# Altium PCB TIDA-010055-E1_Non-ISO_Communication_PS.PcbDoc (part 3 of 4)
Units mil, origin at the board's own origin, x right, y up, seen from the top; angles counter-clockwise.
Board outline 3937.01 x 3346.46 mil, 2 copper layers (Top Layer, Bottom Layer), stack 62 mil thick; 328 components, 142 nets, 761 pads, 214 vias.
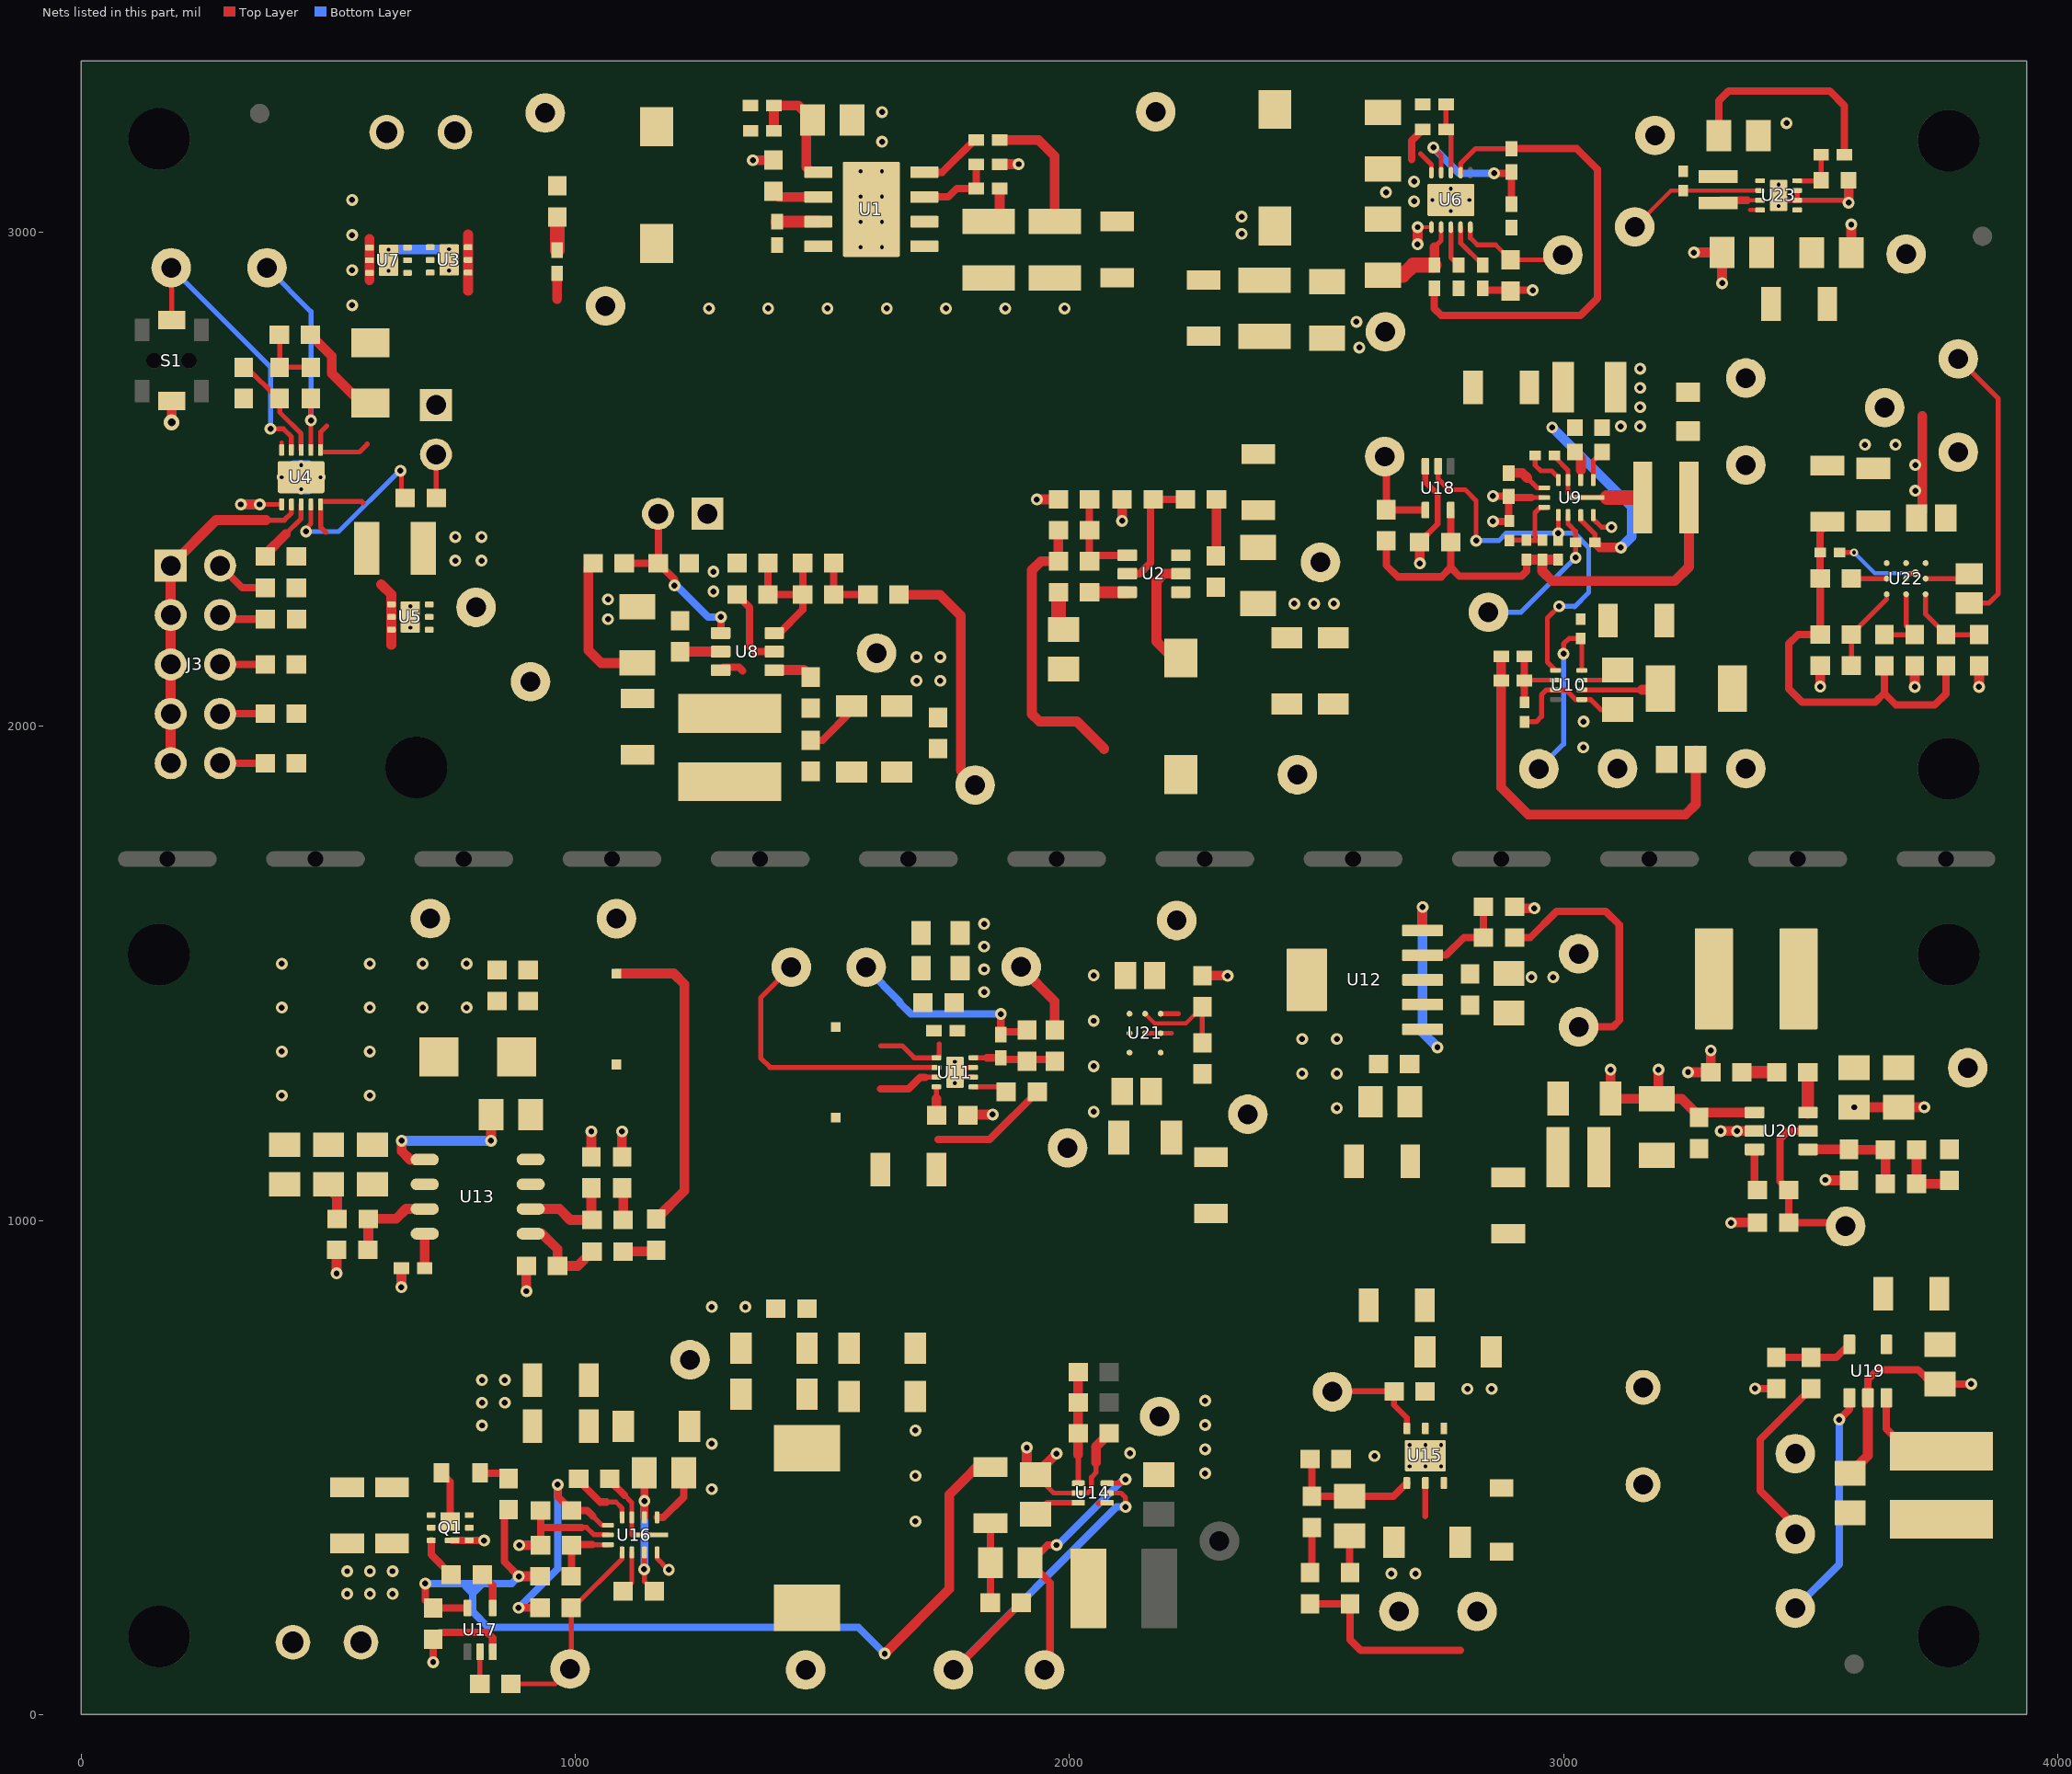
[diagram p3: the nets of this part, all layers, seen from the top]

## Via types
v1: diameter 24, hole 12, Top Layer to Bottom Layer, 179 vias
v2: diameter 19.68, hole 7.87, Top Layer to Bottom Layer, 28 vias
v3: diameter 19.68, hole 7.87, Top Layer to Bottom Layer, tented both sides, 4 vias
v4: diameter 16, hole 8, Top Layer to Bottom Layer, 2 vias
v5: diameter 32, hole 16, Top Layer to Bottom Layer, 1 vias

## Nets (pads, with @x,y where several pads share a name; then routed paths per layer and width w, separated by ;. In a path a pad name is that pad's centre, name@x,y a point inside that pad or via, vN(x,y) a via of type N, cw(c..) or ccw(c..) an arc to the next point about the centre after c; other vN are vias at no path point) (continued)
5V_LMR: C68.1 C69.1 C70.1 C71.1 C72.1 C74.1 L11.2 R63.1 R68.1 R76.2 R78.2 R85.1 R86.1 U17.5 | length 1977.8
  Top Layer w15: v1(696,265) 696,231.5 C74.1@712,215.5 712.2,215.29 U17.5@781.41,215.29 ; R78.2@865,414.5 856,405.5 856,309 v1(885.4,279.6)
  Top Layer w20: v1(885.4,279.6) R76.2@928.5,279.6 ; v1(1626,123) 1757,254 1757,445 1794,482 1813.08,501.08 R63.1@1840.01,501.08
  Bottom Layer w15: v1(696,265) 792,265 ; 777,265 777,260 792,245 811,264 811,265 ; v1(885.4,279.6) 870.8,265 792,265 ; v1(1626,123) 1573,176 824,176 792,208 792,265
5V_S: C25.1 C26.1 C27.2 C28.1 L4.2 R29.2 TP9.1 | length 497.4
  Top Layer w20: R29.2@1654.93,2266.49 1737.51,2266.49 1780,2224 1780,1910.29 TP9.1@1809,1881.29
24V: J5.2 R54.2 R55.2 R56.2 R82.2
  other v1: 538,244 584,244 630,244 538,290 584,290 630,290 811,585 811,631 857,631 811,677 857,677
24V/150MA: C61.1 D2.1 R71.1 R72.1 TP33.1 | length 385.9
  Top Layer w15: R72.1@2486.94,224.05 R71.1@2567.87,224.05 2567.87,151.53 2589.4,130 2791.4,130
+5V_P: C10.1 C11.1 C12.1 L2.2 R10.2 TP3.1 | length 591.1
  Top Layer w20: R10.2@1977.5,2397.3 C12.1@1977.5,2334.3 1942.3,2334.3 1924,2316 1924,2025 1939,2010 2015,2010 2070,1955 2070,1954
DC_I: C14.1 R51.2 R58.1 R59.1 R60.1 R61.1 TP10.1 U4.10 U5.4 U5.5 U5.6 | length 285.3
  Top Layer w10: 495,2392.4 484.15,2403.25 U4.10@484.15,2449.23 484.15,2455.18 567.22,2455.18 570,2452.4
  Top Layer w20: 607,2287.4 627.39,2267.01 U5.4@627.39,2246.94 U5.5@627.39,2221.35 U5.6@627.39,2195.76 627.39,2164.8
EN: R33.1 TP14.1 U9.9 | length 314.6
  Top Layer w10: U9.9@3009.11,2427.67 3009.11,2409.99 3024.32,2394.78 R33.1@3024.32,2372.1 v1(3024.32,2341.41)
  Bottom Layer w10: TP14.1@2848,2231 2913.9,2231 v1(3024.32,2341.41)
EN1: R88.1 R91.2 TP42.1 U20.5 | length 358.5
  Top Layer w15: U20.5@3494.74,1180.94 3453.94,1180.94 3438,1165 3438,1079.31 R88.1@3455.62,1061.69 R91.2@3455.62,995.69 3563.31,995.69 TP42.1@3571,988
FB: C34.2 R35.1 R37.2 U9.7 | length 147.3
  Top Layer w10: R37.2@2890,2376.41 2890.37,2376.78 C34.2@2925,2376.78 2925.69,2376.1 2942,2376.1 ; R35.1@2957,2376.78 2956.32,2376.1 2942,2376.1 ; U9.7@2960.88,2443.41 2953.32,2443.41 2942,2432.1 2942,2376.1
GND: C40.2 C42.2 C43.2 C44.2 C45.2 C46.1 C47.1 C48.1 C49.1 C51.2 C52.2 C53.2 C54.2 C55.2 C56.2 C58.2 C59.2 C60.2 C61.2 C62.2 C66.2 C67.2 C68.2 C69.2 C70.2 C71.2 C72.2 C73.2 C74.2 C76.2 C77.2 C79.2 C80.2 C81.2 C82.2 C83.2 C85.2 C86.2 C87.2 D1.2 J5.1 Q1.4 Q1.7 R42.1 R44.1 R48.1 R49.1 R50.1 R67.1 R73.1 R77.1 R84.1 R91.1 R92.1 R95.1 TP21.1 TP23.1 TP25.1 TP31.1 TP34.1 TP37.1 TP39.1 TP45.1 U11.2 U11.3 U11.9@1767.99,1299.75 U12.3 U12.6 U13.7 U14.2 U15.1 U15.5 U15.7@2720.27,523.66 U16.1 U16.6 U16.11 U17.3 U19.2 U20.1 U21.C1 U21.C2 U21.C3 | length 2923.4
  Top Layer w10: 1012.47,378.53 1022.47,378.53 1036.91,364.09 1065.19,364.09 U16.6@1065.88,363.4 ; U16.11@1165.29,327.97 1165.29,315.71 1188,293 v1(1189,293) ; U11.2@1805.39,1289.91 1777.83,1289.91 U11.9@1767.99,1299.75 1777.83,1309.6 U11.3@1805.39,1309.6 ; C60.2@1931.01,485.19 1968.01,448.19 U14.2@2017.87,448.19 2036.78,448.19 2044.54,455.96 2044.54,480.19 2053.54,489.19 2053.54,509.96
  Top Layer w12: C61.2@2656.94,348.54 C61.2@2656.94,356.42 ; 2720.27,401 U15.5@2720.27,468.54
  Top Layer w15: v1(712,106) C74.2@712,152.5 725.5,166 822,166 832.59,155.41 U17.3@832.59,126.71 ; Q1.7@750.35,352.41 v1@814.59,352.41 ; R77.1@929.5,342.6 929.5,381 ; C73.2@929.5,412.6 929.5,381 ; 1012.47,378.53 931.98,378.53 929.5,381 ; U16.1@1165.29,398.83 1177.83,398.83 1219,440 C67.2@1219,489.4 ; v1(3387.5,659.5) R84.1@3431,659.5 ; U19.2@3616,640.87 3616,678 3636,698 3717,698 3746,669 C76.2@3762,669 v1(3825,669)
  Top Layer w20: v1(516.62,892.91) R48.1@516.62,940.31 ; C56.2@647.6,903.16 647.74,903.02 v1(647.74,864.79) ; v1(886.4,342.6) R77.1@929.5,342.6 ; v1(900.72,856.8) R49.1@900.72,908.16 ; C58.2@1032.22,1128.66 v1(1032.22,1180.26) ; R50.1@1094.22,1128.66 v1(1094.22,1180.26) ; C40.2@1794.49,1212.75 1795.96,1214.23 v1(1844.52,1214.23) ; TP21.1@1902.39,1511.23 1969.99,1443.63 R42.1@1969.99,1385.25 R42.1@1969.99,1381.75 ; v1(1913.54,539.96) 1913.54,502.66 C60.2@1931.01,485.19 v1(1973.77,527.96) ; 2053.54,509.96 2053.54,541.56 2055.07,543.09 2055.07,543.76 R67.1@2080.5,569.19 ; R95.1@2269,1495.5 v1@2319.5,1495.5 ; R44.1@2900.97,1634.85 2904.06,1631.75 v1(2941,1631.75) ; v1(3095.15,1305.15) C81.2@3095.15,1247 3096.12,1246.03 C80.2@3188.61,1246.03 3239.02,1246.03 3276.61,1208.44 3286.51,1218.35 U20.1@3386.47,1218.35 ; C80.2@3192.03,1247 v1(3192.03,1305.15) ; v1(3339,995) 3339.69,995.69 R91.1@3392.62,995.69 ; v1(3530,1082) 3530.99,1081.01 R92.1@3578,1081.01 ; C77.2@3580,488 3616,524 U19.2@3616,640.87 ; v1(3588,1229) C83.2@3678,1229 v1(3730,1229)
  other v1: 2651.4,285 2700.4,285 815,352 1688,391 1276,456 1688,483 2274.54,487.96 2617.4,523 2122.54,528.96 2274.54,536.96 1276,548 1688,575 2274.54,585.96 2274.54,634.96 2805.4,659 2854.4,659 1276,825 1344,825 2049,1220 2541,1227.25 405.74,1252.79 583.74,1252.79 2471,1297.25 2541,1297.25 2049,1312 405.74,1341.79 583.74,1341.79 2471,1367.25 2541,1367.25 2049,1404 405.74,1430.79 583.74,1430.79 690.74,1430.79 779.74,1430.79 1827.39,1462.23 2935,1492.25 2979,1492.25 2320,1495 2049,1496 1827.39,1508.23 405.74,1519.79 583.74,1519.79 690.74,1519.79 779.74,1519.79 1827.39,1554.23 1827.39,1600.23
  other v2: 2688.62,502.01 2720.27,502.01 2751.93,502.01 2688.62,545.32 2720.27,545.32 2751.93,545.32 1767.99,1278.1 1767.99,1321.41
GND_P: C2.2 C5.1 C6.1 C8.2 C9.2 C10.2 C11.2 C13.2 C14.2 C15.2 C16.2 C17.2 C19.2 C20.2 C21.2 C22.2 C25.2 C26.2 C27.1 C28.2 C29.2 C30.1 C31.2 C32.2 C35.2 C36.2 C37.2 C38.2 C75.2 C88.2 C89.2 C91.2 C92.2 C93.2 J2.2 J4.1 R4.1 R5.1 R6.1 R11.1 R12.1 R25.1 R26.1 R27.1 R30.1 R32.1 R37.1 R39.1 R62.1 R99.1 R102.1 R103.1 R108.1 S1.1 TP2.1 TP5.1 TP8.1 TP11.1 TP12.1 TP16.1 TP18.1 TP47.1 TP50.1 U1.1 U1.9@1599,3046.55 U2.1 U4.6 U5.1 U5.2 U5.3 U5.7@665.78,2221.35 U6.10 U6.11 U7.4 U7.5 U7.6 U8.2 U9.1 U9.6 U9.11 U10.3 U10.5 U18.3 U22.C2 U23.2 U23.3 U23.9@3435.31,3074.72 | length 2445.9
  Top Layer w10: v1(360.9,2449.23) U4.6@405.41,2449.23 ; 2711,3158.61 2732.53,3137.08 U6.10@2732.53,3120.65 ; R39.1@2921.37,2009.15 2944.68,2009.15 2955.37,2019.83 2955.37,2063.83 2965.52,2073.99 U10.3@2983.79,2073.99 3004.14,2073.99 3023.82,2054.3 U10.5@3036.94,2054.3 3054.89,2054.3 3075.37,2033.83 C35.2@3109.37,2033.83 ; 2935,2463.1 U9.6@2960.88,2463.1 ; U9.11@3060.29,2427.67 3060.29,2419.81 3077,2403.1 v1(3097,2403.1) ; U9.1@3060.29,2498.53 3060.29,2537.84 C32.2@3077.76,2555.3 ; U23.9@3435.31,3074.72 3445.15,3064.88 U23.2@3472.71,3064.88 ; U23.3@3472.71,3084.57 U23.2@3472.71,3064.88 ; v1(3577,3060) 3572.12,3064.88 U23.2@3472.71,3064.88
  Top Layer w12: C75.2@2708.5,2373 2745,2409.5 2745,2470 2720.41,2494.59 U18.3@2720.41,2526.29
  Top Layer w15: R32.1@1326.93,2266.49 1352.41,2241.02 1352.41,2161.23 1362.32,2151.32 U8.2@1402.34,2151.32 ; C28.2@1476.21,1971.82 1500,1971.82 1559.21,2031.02 C25.2@1559.21,2041.25 ; 2692.5,3147.62 2692.5,3185.62 R26.1@2714.88,3208 ; C20.2@2836.5,2886.38 2840.03,2882.85 v1(2937.68,2882.85) ; v1(2857,2415.1) R37.1@2889,2415.1 ; v1(2857,2466.1) 2888.38,2466.1 C37.2@2889,2465.48 ; R37.1@2890,2415.78 2889,2416.78 C37.2@2889,2465.48 ; 2935,2463.1 2891.38,2463.1 C37.2@2889,2465.48
  Top Layer w20: v5(182.74,2615.31) S1.1@182.74,2658.65 ; v1(322.9,2449.23) v1(360.9,2449.23) ; 583.23,2903.22 U7.6@583.23,2917.81 U7.5@583.23,2943.4 U7.4@583.23,2968.99 583.23,2986.63 ; 963,2865.4 R5.1@963,2916.93 ; v1(1359.13,3145.88) 1400.83,3145.88 C2.2@1401,3146.05 ; R4.1@1858.62,3137.55 1858.94,3137.88 v1(1897.13,3137.88) ; v1(1934,2459.3) R12.1@1977.5,2459.3 ; v1(2106.5,2415.8) R11.1@2106.5,2459.3 ; C75.2@2708.5,2373 2709,2372.5 v1(2709,2330) ; v1(3264,2959) C92.2@3321,2959 v1(3321,2897) v1@3321,2895 ; v1(3519.5,2080.5) R99.1@3519.5,2123 ; R108.1@3576.56,3105 3577,3104.56 v1(3577,3060) ; C91.2@3582.31,2958.72 v1(3582.31,3015.72) ; v1(3711,2080) R102.1@3711,2122.5 ; C89.2@3714.47,2422 3726,2433.53 3726,2628 ; v1(3841,2080) R103.1@3841,2122.5
  other v1: 3040,1957.4 3040.37,2009.83 1690.41,2092.23 1738.41,2092.23 1690.41,2140.23 1738.41,2140.23 1066,2217 2455,2248.3 2495,2248.3 2535,2248.3 1066,2257 1279.41,2273.23 1279.41,2313.23 757,2335.4 810,2335.4 757,2383.4 810,2383.4 3712,2477 3712,2529 3610,2570 3672,2570 3116,2607.1 3155,2607.1 3155,2646.1 3155,2685.1 3155,2724.1 2586.68,2766.85 2580.68,2818.85 1270.13,2845.88 1390.13,2845.88 1510.13,2845.88 1630.13,2845.88 1750.13,2845.88 1870.13,2845.88 1990.13,2845.88 548,2852.4 548,2923.4 548,2994.4 2697.5,3062.62 548,3065.4 2640.68,3080.85 2697.5,3102.62 1620.65,3183.32 3451.31,3221 1620.65,3243.32
  other v2: 665.78,2199.7 665.78,2243 1577.35,3020.96 1620.65,3020.96 2771.9,3042.9 3435.31,3053.07 2734.5,3065.54 2809.3,3065.54 1577.35,3072.14 1620.65,3072.14 2771.9,3088.17 3435.31,3096.38
  other v3: 1577.35,2969.78 1620.65,2969.78 1577.35,3123.32 1620.65,3123.32
NetC1_1: C1.1 U1.7 | length 83.6
  Top Layer w25: C1.1@1408.13,3021.5 1408.18,3021.55 U1.7@1491.72,3021.55
NetC1_2: C1.2 L1.1 U1.8
NetC2_1: C2.1 U1.6 | length 95.5
  Top Layer w20: C2.1@1401,3083.06 1412.5,3071.55 U1.6@1491.72,3071.55
NetC3_2: C3.2 R5.2 | length 66.9
  Top Layer w30: R5.2@963,2964.17 C3.2@963,3031.06
NetC4_2: C4.2 R3.1 R6.2 U1.5 | length 271.4
  Top Layer w20: C4.2@1402,3205.55 1401.62,3205.93 R3.1@1401.62,3256.55 1451,3256.55 R6.2@1480,3227.55 1467.13,3214.68 1467.13,3131.88 1477.45,3121.55 U1.5@1491.72,3121.55
NetC5_2: C5.2 C6.2 R1.2 R2.2 R58.2 U1.2 | length 333.5
  Top Layer w20: C6.2@1836,3021.64 1858.62,3044.26 R2.2@1858.62,3088.55 ; R1.2@1858.62,3186.55 1937.45,3186.55 1970,3154 C5.2@1970,3021.64
NetC7_1: C7.1 L2.1 U2.2 | length 246.5
  Top Layer w20: L2.1@2225,2122.86 2176,2171.86 2176,2293.3 2191.6,2308.9 U2.2@2225.27,2308.9
NetC7_2: C7.2 R7.2 | length 79.3
  Top Layer w30: R7.2@1977.5,2271.3 1977.5,2206.8 C7.2@1988,2196.3
NetC8_1: C8.1 C9.1 R8.2 R59.2 U2.3 | length 115.1
  Top Layer w20: C8.1@2296,2344.8 2297.5,2346.29 R8.2@2297.5,2459.3
NetC12_2: C12.2 R10.1 R12.2 U2.4 | length 206.5
  Top Layer w15: R12.2@2040.5,2459.3 R10.1@2040.5,2397.3 C12.2@2040.5,2334.3 2052.5,2346.3 U2.4@2117,2346.3
NetC13_1: C13.1 J1.1 J2.1 R13.2 U3.4 U3.5 U3.6 U4.1 | length 475.9
  Top Layer w10: 496.78,2608.35 484.15,2595.72 U4.1@484.15,2559.47 484.15,2552.72 486.78,2555.35 562.78,2555.35 578.78,2571.35
  Top Layer w20: R13.2@463.82,2792.35 506.78,2749.39 506.78,2714.35 566.8,2654.33 C13.1@584.78,2654.33 ; 782.71,2881.69 U3.4@782.71,2918.46 U3.5@782.71,2944.06 U3.6@782.71,2969.65 782.71,2995.69
NetC15_1: C15.1 C16.1 C17.1 R16.2 R60.2 U6.2 | length 195
  Top Layer w10: 2738.5,2969.62 2752.22,2983.34 U6.2@2752.22,3010.42
  Top Layer w20: R16.2@2738.5,2933.62 2738.5,2969.62
  Top Layer w30: C17.1@2634.5,2912.95 2674.83,2912.95 2695.5,2933.62 R16.2@2738.5,2933.62
NetC18_1: C18.1 U4.8 | length 134.9
  Top Layer w10: 413.78,2389.35 444.78,2420.35 U4.8@444.78,2449.23
  Top Layer w20: C18.1@372.28,2344.35 372.28,2347.85 413.78,2389.35
NetC18_2: C18.2 R18.1 R20.1 R21.1 R22.1 R23.1 R24.1 U4.5 U4.11@444.78,2504.35 | length 164.2
  Top Layer w8: U4.5@405.41,2559.47 405.41,2575.02
  Bottom Layer w20: v2(405.41,2504.35) 430.02,2528.96 v2(444.78,2528.96) 459.54,2528.96 v2(484.15,2504.35) 459.54,2479.74 v2(444.78,2479.74)
NetC20_1: C20.1 U6.4 | length 95.4
  Top Layer w10: U6.4@2791.59,3010.42 2791.59,2978.54 C20.1@2836.5,2933.62
NetC21_1: C21.1 C22.1 R28.2 R61.2 U8.5 | length 372.2
  Top Layer w20: R28.2@1035.71,2330.32 1026,2320.61 1026,2154.23 1052,2128.23 C21.1@1125.21,2128.23 ; C22.1@1212.21,2150.82 1212.7,2151.32 U8.5@1294.07,2151.32
NetC23_1: C23.1 U8.1 | length 80
  Top Layer w20: U8.1@1402.34,2113.92 1462.22,2113.92 C23.1@1476.41,2099.73
NetC23_2: C23.2 L4.1 U8.6 | length 49.7
  Top Layer w15: U8.6@1294.07,2113.92 1299.72,2119.56 1331.08,2119.56 1338.41,2112.23
NetC24_1: C24.1 R29.1 R31.2 | length 133
  Top Layer w15: C24.1@1522.93,2330.49 R31.2@1522.93,2266.49 R29.1@1591.93,2266.49
NetC24_2: C24.2 C29.1 R31.1 R32.2 U8.3 | length 305.8
  Top Layer w15: C29.1@1389.93,2330.49 R32.2@1389.93,2266.49 R31.1@1459.93,2266.49 ; U8.3@1402.34,2188.72 1412.91,2188.72 1459.93,2235.75 R31.1@1459.93,2266.49 ; C24.2@1459.93,2330.49 R31.1@1459.93,2266.49
NetC30_2: C30.2 C31.1 C32.1 R33.2 R51.1 U9.2 U9.10 | length 505
  Top Layer w10: U9.10@3034.7,2427.67 3034.7,2417.4 3063.69,2388.41 R33.2@3063.69,2372.1 ; U9.2@3034.7,2498.53 3034.7,2518.8 3035,2519.1
  Top Layer w20: C32.1@3022.64,2555.3 3035,2542.94 3035,2519.1 ; R33.2@3063.69,2372.1 3073.78,2362 v1(3116,2362)
  Bottom Layer w20: v1(2977,2605.1) 3138,2444.1 3138,2384 v1(3116,2362)
NetC33_1: C33.1 U9.4 | length 82
  Top Layer w10: C33.1@2942.32,2548.1 2942.32,2528.78 2954,2517.1 2976,2517.1 2989.43,2503.67 U9.4@2989.43,2498.53
NetC33_2: C33.2 L5.1 U9.3 U9.12@3047.02,2463.1 | length 243
  Top Layer w10: C33.2@2981.69,2548.1 2981.69,2545.57 3009.11,2518.15 U9.3@3009.11,2498.53 3009.11,2470.99 3017,2463.1 U9.12@3047.02,2463.1 3088,2463.1
  Top Layer w30: 3088,2463.1 L5.1@3160.35,2463.1
NetC35_1: C35.1 R36.2 R52.1 U10.7 | length 78.1
  Top Layer w10: U10.7@3036.94,2093.67 3095.71,2093.67 C35.1@3109.37,2107.33
NetC39_2: C39.2 R38.1 R39.2 U10.2 | length 156.6
  Top Layer w10: R38.1@2920.99,2092.83 2921.83,2093.67 U10.2@2983.79,2093.67
  Top Layer w15: C39.2@2920.99,2141.83 R38.1@2920.99,2092.83 2920.99,2048.89 R39.2@2921.37,2048.52
NetC40_1: C40.1 R40.1 R53.1 U11.8 | length 297.6
  Top Layer w10: 1730.59,1246.23 U11.8@1730.59,1270.23
  Top Layer w15: 1734,1163.64 1838.43,1163.64 R40.1@1935.01,1260.23
  Top Layer w20: C40.1@1730.59,1213.66 1730.59,1246.23
NetC41_1: C41.1 C42.1 C43.1 C44.1 C45.1 L7.2 R41.2 TP20.1 U11.5 | length 563.9
  Top Layer w10: 1617.99,1353.46 1661.16,1353.46 1685.34,1329.28 U11.5@1730.59,1329.28 1736.39,1335.09 1736.39,1357.23
  Top Layer w15: v1(1860.99,1417.83) C41.1@1860.99,1376.38 1866.37,1381.75 R41.2@1913.99,1381.75
  Bottom Layer w15: TP20.1@1585.99,1510.75 TP20.1@1587.26,1509.49 ; TP20.1@1588.52,1510.75 1657.02,1442.25 1657.02,1439.73 1678.92,1417.83 v1(1860.99,1417.83)
NetC41_2: C41.2 R41.1 R42.2 U11.4 | length 166.1
  Top Layer w10: U11.4@1805.39,1329.28 1832.39,1329.28
  Top Layer w15: 1832.39,1329.28 1832.54,1329.13 C41.2@1860.99,1329.13 1864.37,1325.75 1913.99,1325.75 R42.2@1969.99,1325.75
NetC46_2: C46.2 C48.2 R57.1 U12.1 U12.5 | length 344
  Top Layer w20: U12.5@2714.6,1586.85 v1(2714.6,1634.35)
  Bottom Layer w20: v1(2714.6,1634.35) 2714.6,1380.41 v1(2744.67,1350.34)
NetC47_2: C47.2 C49.2 R43.2 TP22.1 U12.2 | length 526.6
  Top Layer w15: R43.2@2900.97,1572.85 2933.09,1572.85 2986,1625.75 3085.65,1625.75 3112.81,1598.6 3112.81,1404.6 3100.06,1391.85 TP22.1@3030.47,1391.85
NetC50_1: C50.1 D1.1 L8.1 U13.8
NetC50_2: C50.2 U13.1 | length 308.6
  Top Layer w20: v1(648.27,1161.31) 648.27,1140.26 665.37,1123.16 U13.1@694.94,1123.16 ; v1(829.22,1161.31) C50.2@829.22,1214.16
  Bottom Layer w20: v1(648.27,1161.31) v1(829.22,1161.31)
NetC53_1: C53.1 C54.1 C55.1 R46.2 R55.1 R56.1 U13.2 | length 80.1
  Top Layer w20: C54.1@493.22,1073.16 517.72,1048.66 R46.2@517.72,1003.16
NetC56_1: C56.1 U13.4 | length 70
  Top Layer w20: C56.1@694.84,903.16 694.94,903.26 U13.4@694.94,973.16
NetC57_1: C57.1 C58.1 U13.6 | length 198.5
  Top Layer w20: U13.6@909.5,1023.16 967.37,1023.16 989.37,1001.16 C57.1@1033.72,1001.16 1032.22,1002.67 C58.1@1032.22,1065.67
NetC57_2: C57.2 R50.2 | length 65.5
  Top Layer w20: R50.2@1094.22,1065.67 1096.72,1063.17 C57.2@1096.72,1001.16
NetC60_1: C60.1 R63.2 R64.1 R65.2 U14.3 | length 257.8
  Top Layer w11: C60.1@1931.01,405.19 1954.32,428.51 U14.3@2017.87,428.51
  Top Layer w15: R64.1@1839.51,226.19 1840.01,226.69 R65.2@1840.01,307.19 ; R65.2@1840.01,307.19 R63.2@1840.01,387.3
NetC62_1: C62.1 L10.1 R68.2 R69.1 U15.2
NetC63_1: C63.1 R70.1 R73.2 U15.4 | length 280.6
  Top Layer w15: R73.2@2486.87,516.96 2490.37,513.47 C63.1@2490.37,441.54 R70.1@2566.87,441.54 2655.87,441.54 U15.4@2682.87,468.54
NetC63_2: C63.2 R72.2 | length 92.9
  Top Layer w15: R72.2@2486.94,287.04 2490.37,290.47 C63.2@2490.37,378.55
NetC64_2: C64.2 R66.1 R67.2 U14.1 | length 225.5
  Top Layer w11: 2017.51,525.96 2017.51,468.24 U14.1@2017.87,467.88
  Top Layer w20: 2017.51,525.96 R67.2@2017.51,569.19 ; R67.2@2017.51,569.19 C64.2@2017.51,693.19
NetC65_1: C65.1 U16.4 | length 133.7
  Top Layer w10: 1063,430 1082,430 1094.43,417.57 U16.4@1094.43,398.83
  Top Layer w15: C65.1@1006.5,477.4 1006.5,473.5 1050,430 1063,430
NetC65_2: C65.2 L11.1 TP35.1 U16.3 U16.12@1152.02,363.4 | length 170.4
  Top Layer w10: 1099,444 1114.11,428.89 U16.3@1114.11,398.83 1114.11,363.4 U16.12@1152.02,363.4
  Top Layer w15: C65.2@1069.5,477.4 1069.5,473.5 1099,444
NetC66_1: C66.1 C67.1 R54.1 R74.2 R82.1 U16.2 U16.10 | length 311
  Top Layer w10: U16.10@1139.7,327.97 1139.7,269.2 R74.2@1159.5,249.4
  Top Layer w15: C67.1@1139,489.4 1139.7,488.7 v1(1139.7,432) U16.2@1139.7,398.83
  Bottom Layer w15: v1@1139.7,298.58 v1(1139.7,432)
  other v1: 1139,294
NetC76_1: C76.1 R85.2 U19.4
NetC77_1: C77.1 L12.2 R83.2 TP26.1 | length 366.6
  Top Layer w15: TP26.1@3469,365 3469,382 3398,453 3398,556.5 R83.2@3501,659.5
NetC78_1: C78.1 R87.2 | length 70.5
  Top Layer w25: C78.1@3360.99,1300 R87.2@3431.5,1300
NetC78_2: C78.2 L14.1 U20.2 | length 158.5
  Top Layer w20: v1(3252,1300) C78.2@3298,1300 v1(3298,1344) ; v1(3318,1181) 3318.06,1180.94 v1(3351.06,1180.94) U20.2@3386.47,1180.94
NetC79_1: C79.1 C80.1 L13.2 R88.2 U20.3 | length 84.4
  Top Layer w15: U20.3@3386.47,1143.54 3386.47,1067.84 R88.2@3392.62,1061.69
NetC81_1: C81.1 L13.1 R86.2
NetC82_1: C82.1 C83.1 L14.2 R90.2 TP41.1
NetC84_1: C84.1 R89.2 R90.1 | length 138.4
  Top Layer w20: R89.2@3714.5,1143 C84.1@3714.5,1074 3773.99,1074 R90.1@3781,1081.01
NetC84_2: C84.2 R89.1 R92.2 U20.4 | length 226.4
  Top Layer w20: U20.4@3494.74,1143.54 3495.2,1144 R92.2@3578,1144 3579,1143 R89.1@3651.5,1143 C84.2@3651.5,1074
NetC85_1: C85.1 C86.1 R93.1 R94.2 TP43.1 U21.A2 U21.A3 U21.B2 | length 53
  Top Layer w10: U21.B2@2153,1379 U21.A2@2184.5,1379 2206,1379
NetC87_1: C87.1 TP44.1 U21.A1 | length 35.4
  Top Layer w10: U21.A1@2184.5,1418.37 2219.93,1418.37
NetC89_1: C89.1 TP46.1 U22.C1
NetC90_1: C90.1 U22.B1 | length 92.2
  Top Layer w10: U22.B1@3732.74,2299 3811.47,2299 C90.1@3821,2308.53
NetC90_2: C90.2 TP48.1 | length 575.6
  Top Layer w10: TP48.1@3799,2744 3880,2663 3880,2269 3860.47,2249.47 C90.2@3821,2249.47
NetC91_1: C91.1 C92.1 R105.2 U23.1 U23.8 | length 20.9
  Top Layer w8: 3377,3045.2 U23.8@3397.91,3045.2
NetC93_1: C93.1 L15.2 R106.2 R107.2 TP49.1 U23.5 | length 444.7
  Top Layer w15: C93.1@3314.31,3195.72 3314.31,3266.31 3334,3286 3539,3286 3568.62,3256.38 R106.2@3568.62,3157
NetD2_2: D2.2 L10.2 U15.6
NetD3_1: D3.1 Q1.1 Q1.2 Q1.5 Q1.6 Q1.8 | length 105.7
  Top Layer w15: D3.1@728.63,489 746.61,471.02 Q1.8@746.61,390.8
NetD3_2: D3.2 R78.1 | length 68.9
  Top Layer w15: D3.2@807.37,489 808.37,488 854.5,488 R78.1@865,477.5 ; R78.1@865,475 R78.1@871.5,475
NetJ1_2: J1.2 R9.2 | length 88.2
  Top Layer w10: J1.2@717.78,2550.35 718.28,2549.85 R9.2@718.28,2462.35
NetJ3_1: J3.1 J3.3 J3.5 J3.7 J3.9 U4.7 | length 724.9
  Top Layer w10: 373.78,2417.35 410.78,2417.35 425.1,2431.67 U4.7@425.1,2449.23
  Top Layer w20: J3.9@180.78,1925.35 J3.7@180.78,2025.35 J3.5@180.78,2125.35 J3.3@180.78,2225.35 J3.1@180.78,2325.35 J3.1@183.78,2328.35 ; J3.1@183.78,2309.35 J3.1@183.78,2328.35 ; 373.78,2417.35 272.78,2417.35 J3.1@183.78,2328.35
NetJ3_2: J3.2 R20.2 | length 110.1
  Top Layer w15: J3.2@280.78,2325.35 325.78,2280.35 R20.2@372.28,2280.35
NetJ3_4: J3.4 R21.2 | length 96.6
  Top Layer w15: J3.4@281.78,2226.35 J3.4@280.78,2225.35 289.13,2217 R21.2@372.5,2217
NetJ3_6: J3.6 R22.2 | length 91.5
  Top Layer w15: J3.6@280.78,2125.35 R22.2@372.28,2125.35
NetJ3_8: J3.8 R23.2 | length 91.5
  Top Layer w15: J3.8@280.78,2025.35 R23.2@372.28,2025.35
NetJ3_10: J3.10 R24.2 | length 91.5
  Top Layer w15: J3.10@280.78,1925.35 R24.2@372.28,1925.35
NetJ4_2: J4.2 R28.1 R30.2 U8.4 | length 381
  Top Layer w15: R28.1@1098.7,2330.32 R30.2@1167.71,2330.32 ; J4.2@1167.21,2430.32 1167.71,2429.82 R30.2@1167.71,2330.32 ; v1(1200.41,2285.23) 1200.41,2297.62 R30.2@1167.71,2330.32 ; U8.4@1294.07,2188.72 1294.41,2189.06 v1(1294.41,2221.23)
  Bottom Layer w15: v1(1200.41,2285.23) 1204.41,2285.23 1268.41,2221.23 v1(1294.41,2221.23)
NetL3_1: L3.1 U6.1 | length 62.7
  Top Layer w8: v1(2704.7,3010.42) U6.1@2732.53,3010.42
  Top Layer w20: v1(2704.5,2975.62) 2704.7,2975.83 v1(2704.7,3010.42)
  other v1: 2348.3,2996.83 2348.5,3031.62
NetL6_1: L6.1 U10.6 | length 160.2
  Top Layer w10: U10.6@3036.94,2073.99 3159,2073.99
  Top Layer w20: 3159,2073.99 3193.75,2073.99 L6.1@3196.17,2076.4
NetL7_1: L7.1 U11.7 | length 122.2
  Top Layer w10: 1708.39,1289.91 U11.7@1730.59,1289.91
  Top Layer w15: 1617.99,1266.05 1674.53,1266.05 1697.7,1289.22 1708.39,1289.22
NetL9_1: L9.1 U14.4 | length 18.3
  Top Layer w10: 2058.48,426.96 2060.03,428.51 U14.4@2076.14,428.51
NetL12_1: L12.1 U19.3 | length 192.8
  Top Layer w15: U19.3@3653.4,640.87 3653.4,578.6 3699.1,532.9 L12.1@3765,532.9
NetL15_1: L15.1 U23.7 | length 87.2
  Top Layer w8: 3372,3064.88 U23.7@3397.91,3064.88
  Top Layer w15: L15.1@3313,3059.43 3318.46,3064.88 3372,3064.88
NetQ1_3: Q1.3 R80.1 | length 86.1
  Top Layer w15: Q1.3@708.23,352.41 708.23,323.28 R80.1@748.5,283
NetR1_1: R1.1 U1.4 | length 132
  Top Layer w15: U1.4@1706.28,3121.55 1742.5,3121.55 1807.5,3186.55 R1.1@1811.38,3186.55
NetR2_1: R2.1 R4.2 U1.3 | length 161.1
  Top Layer w15: U1.3@1706.28,3071.55 1754.8,3071.55 1771.8,3088.55 R2.1@1811.38,3088.55 R4.2@1811.38,3137.55
NetR7_1: R7.1 U2.6 | length 76.6
  Top Layer w25: R7.1@2040.5,2271.3 2040.69,2271.5 U2.6@2117,2271.5
NetR8_1: R8.1 R11.2 U2.5 | length 251.6
  Top Layer w15: U2.5@2117,2308.9 2141.6,2308.9 2164,2331.3 2164,2453.8 R11.2@2169.5,2459.3 R8.1@2234.5,2459.3
NetR9_1: R9.1 U4.9 | length 364.3
  Top Layer w10: v1(454.78,2394.35) 451.78,2397.35 464.47,2410.04 U4.9@464.47,2449.23 ; v1(645.78,2517.35) 647.78,2517.35 647.78,2469.85 R9.1@655.28,2462.35
  Bottom Layer w10: v1(454.78,2394.35) 520.78,2394.35 644.78,2518.35 v1(645.78,2517.35)
NetR13_1: R13.1 R14.1 R15.2 | length 128.7
  Top Layer w10: R13.1@400.83,2792.35 401.32,2791.85 R15.2@401.32,2726.85 R14.1@464.32,2726.85
NetR14_2: R14.2 TP6.1 U4.2 | length 450.3
  Top Layer w10: R14.2@464.32,2663.85 464.47,2663.71 U4.2@464.47,2559.47
  Bottom Layer w10: TP6.1@375.78,2928.35 464.78,2839.35 v1(464.78,2619.35)
NetR15_1: R15.1 R18.2 U4.3 | length 221.5
  Top Layer w10: R18.2@328.32,2726.85 334.28,2726.85 397.28,2663.85 R15.1@401.32,2663.85 401.32,2635.81 444.78,2592.35 U4.3@444.78,2559.47
NetR16_1: R16.1 R19.2 U6.7 | length 970.5
  Top Layer w10: U6.7@2791.59,3120.65 2791.59,3138.71 2822.04,3169.16 R19.2@2887.5,3169.16
  Top Layer w15: R16.1@2738.5,2886.38 2738.5,2845.62 2752.5,2831.62 3034.46,2831.62 3068.68,2865.85 3068.68,3127.32 3026.84,3169.16 R19.2@2894.5,3169.16
NetR17_1: R17.1 R26.2 U6.8 | length 142.4
  Top Layer w10: R17.1@2762.12,3259 R26.2@2762.12,3208 2771.9,3198.22 U6.8@2771.9,3120.65
NetR19_1: R19.1 R27.2 U6.9 | length 303.3
  Top Layer w10: v1(2736.5,3171.62) 2752.22,3155.91 U6.9@2752.22,3120.65
  Top Layer w15: v1(2859.5,3119.62) 2892.21,3119.62 R19.1@2894.5,3121.91 R27.2@2894.5,3056.62
  Bottom Layer w15: v1(2736.5,3171.62) 2788.5,3119.62 v1(2859.5,3119.62)
NetR25_2: R25.2 U6.3 | length 83.3
  Top Layer w10: U6.3@2771.9,3010.42 2771.9,2949.22 R25.2@2787.5,2933.62
NetR36_1: R36.1 TP17.1 U10.8 | length 378.3
  Top Layer w10: v1(3000,2147) 3000,2167 3010.83,2177.83 R36.1@3034.68,2177.83 3036.94,2175.57 U10.8@3036.94,2113.36
  Bottom Layer w10: TP17.1@2950,1914 3000,1964 v1(3000,2147)
NetR40_2: R40.2 U11.1 | length 70.8
  Top Layer w10: U11.1@1805.39,1270.23 1862.02,1270.23 R40.2@1872.02,1260.23
NetR43_1: R43.1 R44.2 U12.4 | length 200.3
  Top Layer w15: U12.4@2714.6,1536.85 2762.6,1536.85 2798.6,1572.85 R43.1@2837.98,1572.85 R44.2@2837.98,1634.85
NetR45_1: R45.1 R47.2 | length 67.5
  Top Layer w20: R47.2@1096.72,937.16 1160.72,937.16 R45.1@1163.22,939.67
NetR46_1: R46.1 R48.2 U13.3 | length 188.6
  Top Layer w20: R48.2@582.22,937.66 580.72,939.16 R46.1@580.72,1003.16 637.12,1003.16 657.12,1023.16 U13.3@694.94,1023.16
NetR47_1: R47.1 R49.2 U13.5 | length 182.9
  Top Layer w20: U13.5@909.5,973.16 932.37,973.16 963.72,941.81 R49.2@963.72,908.16 1004.72,908.16 R47.1@1033.72,937.16
NetR62_2: R62.2 TP27.1 U6.5 | length 231.4
  Top Layer w10: U6.5@2811.27,3010.42 2811.27,2988.85 2825.5,2974.62 2862.41,2974.62 R62.2@2892.68,2944.35 2989.18,2944.35 TP27.1@2998.68,2953.85
NetR64_2: R64.2 TP28.1 U14.5 | length 739.4
  Top Layer w10: U14.5@2076.14,448.19 2104.31,448.19 2113.54,438.96 v1(2113.54,419.96)
  Top Layer w15: TP28.1@1765,90 1766.31,90 R64.2@1902.5,226.19
  Bottom Layer w15: TP28.1@1765,90 2094.96,419.96 v1(2113.54,419.96)
NetR65_1: R65.1 TP30.1 U14.6 | length 546.1
  Top Layer w10: U14.6@2076.14,467.88 2105.46,467.88 v1(2113.54,475.96)
  Top Layer w15: TP30.1@1949.54,90 1960.54,101 1960.54,266.66 R65.1@1920.01,307.19 1955.81,343 v1(1974,343)
  Bottom Layer w15: v1(1974,343) 1974,340.59 2109.37,475.96 v1(2113.54,475.96)
NetR69_2: R69.2 TP32.1 U15.3 | length 209.5
  Top Layer w12: TP32.1@2533.4,654 R69.2@2656.91,654 2656.91,626.5 2682.87,600.53 U15.3@2682.87,578.78
NetR70_2: R70.2 R71.2 | length 74.9
  Top Layer w15: R70.2@2566.87,361.54 2566.87,288.04 R71.2@2567.87,287.04
NetR74_1: R74.1 U16.9 | length 85.9
  Top Layer w10: R74.1@1096.5,249.4 1114.11,267.01 U16.9@1114.11,327.97
NetR76_1: R76.1 R77.2 U16.7 | length 137.3
  Top Layer w10: 1033.72,343.72 U16.7@1065.88,343.72
  Top Layer w15: R76.1@991.5,279.6 992.5,280.6 R77.2@992.5,342.6 993.61,343.72 1033.72,343.72
NetR79_2: R79.2 U17.2 | length 64.9
  Top Layer w10: R79.2@806.5,62 806.5,126.21 U17.2@807,126.71
NetR80_2: R80.2 U17.4 | length 76.4
  Top Layer w15: R80.2@811.5,283 832.59,261.91 U17.4@832.59,215.29
NetR81_1: R81.1 TP38.1 U18.4 | length 188.5
  Top Layer w12: TP38.1@2638,2546 TP38.1@2641,2543 ; R81.1@2641,2438.5 R81.1@2641.79,2437.71
  Top Layer w15: R81.1@2641,2438.5 TP38.1@2641,2543 ; R81.1@2641.79,2437.71 U18.4@2720.41,2437.71
NetR83_1: R83.1 R84.2 U19.5 | length 158.6
  Top Layer w15: R84.2@3431,722.5 R83.1@3501,722.5 3551.96,722.5 U19.5@3578.6,749.13
NetR87_1: R87.1 U20.6 | length 81.4
  Top Layer w25: U20.6@3494.5,1218.59 R87.1@3494.5,1300
NetR94_1: R94.1 R95.2 U21.B1 | length 210.9
  Top Layer w8: U21.B1@2153,1418.37 2172.37,1399 2235.5,1399 R95.2@2269,1432.5
  Top Layer w10: R94.1@2269,1359.5 R95.2@2269,1432.5
NetR98_2: R98.2 U22.B3 | length 71.5
  Top Layer w10: R98.2@3582.5,2299 U22.B3@3654,2299
NetR104_2: R104.2 U22.B2 | length 193.9
  Top Layer w8: U22.B2@3693.37,2299 3704.37,2310 v4(3712,2310)
  Top Layer w10: R104.2@3558.69,2352 v4(3588,2352)
  Bottom Layer w8: v4(3588,2352) 3630,2310 v4(3712,2310)
NetR106_1: R106.1 R108.2 U23.4 | length 101.1
  Top Layer w10: U23.4@3472.71,3104.25 3520.69,3104.25 R108.2@3521.44,3105 3521.44,3156.94 R106.1@3521.38,3157
NetR107_1: R107.1 TP51.1 U23.6 | length 284.4
  Top Layer w8: TP51.1@3144,3011 3217.31,3084.32 R107.1@3242,3084.32 3242.25,3084.57 U23.6@3397.91,3084.57
NetS1_2: S1.2 TP4.1 U4.4 | length 591.6
  Top Layer w10: TP4.1@181.78,2928.35 182.74,2927.39 S1.2@182.74,2822.04 ; v1(382.78,2602.35) 408.78,2602.35 425.1,2586.04 U4.4@425.1,2559.47
  Bottom Layer w10: TP4.1@181.78,2928.35 382.78,2727.35 v1(382.78,2602.35)
NetTP19_1: TP19.1 U11.6 | length 573.2
  Top Layer w10: TP19.1@1437,1512.64 1375,1450.64 1375,1328.64 1394.05,1309.6 U11.6@1730.59,1309.6
NetTP40_1: TP40.1 U19.1 | length 471.3
  Top Layer w15: v1(3558,597) 3578.6,617.6 U19.1@3578.6,640.87
  Bottom Layer w15: TP40.1@3469,215 3558,304 v1(3558,597)
NetU3_1: U3.1 U3.2 U3.3 U3.7@744.33,2944.06 U7.1 U7.2 U7.3 U7.7@621.61,2943.4 | length 209.6
  Bottom Layer w20: v2(621.61,2921.75) v2(621.61,2965.06) 743.68,2965.06 v2(744.33,2965.71) v2(744.33,2922.4)
PG: R75.2 R79.1 TP36.1 U16.8 | length 413.6
  Top Layer w10: R79.1@869.5,62 959,62 TP36.1@989,92 ; TP36.1@991.5,106 R75.2@991.5,216 995,216 1094.43,315.43 U16.8@1094.43,327.97
  Top Layer w15: TP36.1@989,92 991.5,94.5 TP36.1@991.5,106
PGOOD: R34.2 U9.8 U10.1 U18.2 | length 808.6
  Top Layer w10: U18.2@2746,2526.29 2746,2501 2768,2479 2801,2479 2823,2457 v1(2823,2376) ; U10.1@2983.79,2113.36 2967.26,2129.89 2967.26,2219.26 v1(2991,2243) ; R34.2@2989,2376.78 2989.43,2377.21 v1(2989.43,2391.1) U9.8@2989.43,2427.67
  Bottom Layer w10: v1(2823,2376) 2869,2376 2884.1,2391.1 v1(2989.43,2391.1) 3021.9,2391.1 3051,2362 3051,2271 3021.99,2241.99 3020.98,2243 v1(2991,2243)
VCC: C37.1 U9.5 | length 84.3
  Top Layer w10: 2926,2503.1 2946.32,2482.78 U9.5@2960.88,2482.78
  Top Layer w20: C37.1@2889,2512.72 2916.38,2512.72 2926,2503.1
VCC_P: C3.1 C4.1 L1.2 R3.2 TP1.1
VCC_PULLUP: C73.1 R75.1 U16.5 | length 475.4
  Top Layer w10: 1035,402 1053.91,383.09 U16.5@1065.88,383.09
  Top Layer w15: v1(885,216) R75.1@928.5,216 ; v1(964,465) 964,441.1 C73.1@992.5,412.6 992.89,413 1024,413 1035,402
  Bottom Layer w15: v1(885,216) 964,295 v1(964,465)
VIn1: C88.1 R96.2 R97.2 R98.1 R100.2 R101.2 R104.1 U22.C3 | length 866.8
  Top Layer w15: R96.2@3539,2414.11 3519.31,2394.43 R104.1@3519.31,2352 3519.31,2299.19 R98.1@3519.5,2299 R97.2@3519.5,2186 3475,2186 3456,2167 3456,2076 3483,2049 3631,2049 3649,2067 ; R100.2@3649,2122.5 3649,2067 ; R101.2@3774,2122.5 3774,2066 3751,2043 3673,2043 3649,2067
VO1: C34.1 C36.1 C75.1 L5.2 R34.1 R35.2 R52.2 R81.2 R96.1 R105.1 TP13.1 U18.5 | length 1046.4
  Top Layer w15: R81.2@2641,2375.5 2641,2326 2664.37,2302.63 2752.63,2302.63 2771.5,2321.5 ; C75.1@2771.5,2373 2771.5,2321.5 ; C75.1@2771.59,2373.09 U18.5@2771.59,2437.71 ; C34.1@2925,2337.41 2925,2314 2915,2304 2788.99,2304 2771.5,2321.5
  Top Layer w20: C34.1@2925,2337.41 R35.2@2957,2337.41 ; R34.1@2989,2337.41 R35.2@2957,2337.41 ; L5.2@3253.65,2463.1 3253.65,2322.75 3225,2294.1 2977,2294.1 2957,2314.1 R35.2@2957,2337.41
VO2: C51.1 C52.1 L8.2 R45.2 R53.2 R57.2 R93.2 TP24.1 | length 645.5
  Top Layer w20: L8.2@1083.33,1499.71 1198.82,1499.71 1220.74,1477.79 1220.74,1060.18 R45.2@1163.22,1002.66
VO3: C38.1 C39.1 L6.2 R38.2 TP15.1 | length 800.6
  Top Layer w20: C39.1@2873.74,2141.83 R38.2@2873.74,2092.83 2873.74,1876.26 2928.6,1821.4 3247,1821.4 3267.89,1842.29 C38.1@3267.89,1951.83
VOUT_DCDC_P: C19.1 L3.2 R17.2 TP7.1
VSEL1: R97.1 R99.2 U22.A3 | length 174.1
  Top Layer w10: R99.2@3582.5,2123 R97.1@3582.5,2186 3654,2257.5 U22.A3@3654,2267.5
VSEL2: R100.1 R102.2 U22.A2 | length 151.3
  Top Layer w10: R100.1@3649,2185.5 R102.2@3711,2185.5 3693.37,2203.13 U22.A2@3693.37,2267.5
VSEL3: R101.1 R103.2 U22.A1 | length 166.1
  Top Layer w10: U22.A1@3732.74,2267.5 3732.74,2226.76 R101.1@3774,2185.5 R103.2@3841,2185.5
pads on no net: FID1.1 FID2.1 FID3.1 H1.1 H2.1 H3.1 H4.1 H5.0 H6.0 H7.0 H8.0 H9.1 H10.1 H11.1 H12.1 H13.0 H14.0 H15.0 H16.0 LBL1.0 Q1.0 S1.MH1 S1.MH2 S1.MP1 S1.MP2 S1.MP3 S1.MP4 U1.9@1599,3046.55 U3.7@744.33,2926.34 U3.7@744.33,2961.77 U4.11@384.54,2494.51 U4.11@384.54,2514.19 U4.11@419.98,2504.35 U4.11@469.58,2504.35 U4.11@505.02,2494.51 U4.11@505.02,2514.19 U5.7@665.78,2203.63 U5.7@665.78,2239.07 U6.6 U7.7@621.61,2925.69 U7.7@621.61,2961.12 U9.12@3027.02,2463.1 U9.12@3066.98,2463.1 U10.4 U11.9@1767.99,1282.04 U11.9@1767.99,1317.47 U15.7@2697.83,523.66 U15.7@2742.71,523.66 U16.12@1132.02,363.4 U16.12@1171.98,363.4 U17.1 U18.1 U23.9@3435.31,3057.01 U23.9@3435.31,3092.44

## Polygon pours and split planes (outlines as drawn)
GND_P on Top Layer "n" (solid, pour order 232): 3590,2686 3602,2698 3721,2698 3737,2682 3737,2391 3709,2363 3709,2328 3702,2321 3690,2321 3686,2325 3686,2484 3679,2491 3601,2491 3590,2502
NetC89_1 on Top Layer "n" (solid, pour order 230): 3748,2383 3725,2360 3725,2327 3729,2323 3763,2323 3846,2406 3846,2586 3837,2595 3758,2595 3748,2585
VIn1 on Top Layer "n" (solid, pour order 228): 3664,2353 3664,2326 3660,2322 3622,2322 3619,2325 3619,2364 3605,2378 3504,2378 3499,2383 3499,2442 3502,2445 3657,2445 3664,2438
5V_LMR on Top Layer "n" (solid, pour order 226): 1399,491 1399,593 1444,638 1444,885 1469.5,910.5 2491.5,910.5 2587,1006 3213,1006 3311,908 3658,908 3672,894 3672,819 3663,810 3254,810 3149,915 2678,915 2628,865 2628,792 2621,785 1902,785 1882,765 1882,479.97 1876.03,474 1787,474 1782,479 1782,802 1766,818 1593,818 1582,807 1582,497 1570,485 1405,485
NetC81_1 on Top Layer "n" (solid, pour order 224): 3010,1060 2855,1060 2847,1068 2847,1280 2857,1290 3012,1290 3019,1283 3019,1069
NetC87_1 on Top Layer "n" (solid, pour order 222): 2150,1653 2163,1666 2276,1666 2281,1661 2281,1580 2224,1523 2224,1413 2220,1409 2178,1409 2172,1415 2172,1445 2150,1467
GND on Top Layer "n" (solid, pour order 220): 2130,1096 2111,1077 1945,1077 1930,1092 1930,1169 2021,1260 2021,1528 2036,1543 2119,1543 2130,1532
NetC85_1 on Top Layer "n" (solid, pour order 218): 2417,1116 2407,1106 2178,1106 2145,1139 2145,1383 2149,1387 2204,1387 2211,1380 2211,1324 2216,1319 2389,1319 2417,1291
VO2 on Top Layer "gn" (solid, pour order 216): 885.74,1423.79 885.74,1649.79 901.74,1665.79 1291.86,1665.79 1340,1617.64 1340,1081.64 1384,1037.64 1560.81,1037.64 1570,1046.83 1570,1141.64 1574,1145.64 1640.77,1145.64 1648.81,1137.6 1648.81,1046.83 1658,1037.64 2423.64,1037.64 2543,1157 2611,1157 2619,1149 2619,1101 2474,956 2215.36,956 2215,955.64 1301,955.64 1251,1005.64 1251,1516.64 1204,1563.64 1135,1563.64 1129,1557.64 1129,1531.64 1133,1527.64 1190.89,1527.64 1202.33,1516.2 1202.33,1432.79 1193.33,1423.79
GND on Top Layer "gn" (solid, pour order 214): 1166.74,1209.79 989.74,1209.79 968.74,1188.79 968.74,1104.79 951.74,1087.79 864.74,1087.79 789.74,1162.79 789.74,1401.79 800.74,1412.79 856.74,1412.79 863.74,1419.79 863.74,1647.79 845.74,1665.79 56.79,1665.79 36,1645 36,55.64 56.34,35.3 459.3,35.3 476,52 475,53 475,404 308,571 308,1107 325.64,1124.64 613.6,1124.64 619.74,1130.79 619.74,1175.79 632.74,1188.79 693.74,1188.79 752.74,1129.79 752.74,866.79 746.74,860.79 670.74,860.79 663.74,867.79 663.74,948.79 646.74,965.79 488.74,965.79 479.56,956.6 479.56,839.09 509,809.64 900,809.64 924.74,834.39 924.74,931.79 918.74,937.79 870.74,937.79 862.74,945.79 862.74,1047.79 871.74,1056.79 982.74,1056.79 993.74,1067.79 993.74,1099.79 998.74,1104.79 1166.74,1104.79 1174.74,1112.79 1174.74,1201.79
NetC53_1 on Top Layer "gn" (solid, pour order 212): 722.74,1050.79 634.62,1050.79 623,1039.16 468.16,1039.16 455,1026 455,694 668,481 668,432 664,428 508,428 332,604 332,1087 345,1100 719.53,1100 727.74,1091.79 727.74,1055.79
24V/150MA on Top Layer "gn" (solid, pour order 178): 2766,377 2766,115 2773,108 2920,108 2928,116 2928,370 2913,385 2770,385 2766,381
GND on Top Layer "gn" (solid, pour order 172): 1191,514 1191,784 1221,814 1267,860 1324,860 1421,860 1428,853 1428,797 1412,781 1374,781 1363,770 1363,477 1376,464 1645,464 1651,470 1651,786 1656,791 1725,791 1731,785 1731,378 1715,362 1378,362 1338,402 1329,411 1230,411 1199,411 1191,419
NetC65_2 on Top Layer "gn" (solid, pour order 168): 1128,356 1191,356 1217.5,329.5 1217.5,140.5 1311,47 1362,47 1470,47 1538,47 1553,62 1553,251 1523,281 1399,281 1299,381 1188,381 1111,381 1107,377 1107,360 1110,357 1111,356
24V on Top Layer "gn" (solid, pour order 160): 499,364 499,215 499,92 506,85 664,85 669,90 669,370 664,375 504,375 499,370
GND on Top Layer "gn" (solid, pour order 90): 1773.39,1198.23 1773.39,1240.23 1747.39,1266.23 1747.39,1612.23 1747.39,1620.23 1751.39,1624.23 1752.39,1625.23 1765.39,1625.23 1939.39,1625.23 1958.39,1606.23 1958.39,1472.23 1932.39,1446.23 1813.39,1446.23 1802.39,1435.23 1802.39,1368.23 1788.39,1354.23 1786.39,1352.23 1786.39,1305.23 1786.39,1276.6 1822.97,1240.02 1822.97,1198.68 1812.52,1188.23 1773.39,1188.23
GND on Top Layer "gn" (solid, pour order 86): 2637,1248.25 2637,1207.67 2629.17,1199.85 2540.15,1199.85 2438,1302 2438,1450.25 2438,1554.25 2450,1566.25 2619,1566.25 2637,1548.25 2637,1515.25 2645,1507.25 2766,1507.25 2791,1532.25 2878,1532.25 2953,1532.25 2962,1541.25 2962,1601.25 2966,1605.25 3072,1605.25 3087,1590.25 3087,1492.25 3074,1479.25 3068,1473.25 2914,1473.25 2646,1473.25 2637,1464.25
NetC47_2 on Top Layer "gn" (solid, pour order 84): 2770,1458.25 3076,1458.25 3087,1447.25 3087,1339.25 3077,1329.25 2855.89,1329.25 2784.27,1400.87 2763.89,1421.25 2669,1421.25 2665,1425.25 2665,1455.25 2668,1458.25
NetC46_2 on Top Layer "gn" (solid, pour order 78): 2758,1397.25 2758,1086.79 2751.81,1080.6 2671.81,1080.6 2663,1089.41 2663,1392.25 2670,1399.25 2756,1399.25
GND_P on Top Layer "gn" (solid, remove dead copper, pour order 56): 1735.41,1995.23 1534.36,1995.23 1525.41,2004.18 1525.41,2123.23 1514.41,2134.23 1410.41,2134.23 1390.01,2134.23 1379.73,2144.51 1379.73,2159.55 1386.41,2166.23 1441.41,2166.23 1458.41,2183.23 1483.41,2208.23 1590.41,2208.23 1744.77,2208.23 1766.41,2186.59 1766.41,2032.23 1766.41,2001.23 1760.41,1995.23
5V_S on Top Layer "gn" (solid, remove dead copper, pour order 54): 1262.41,1840.23 1845.83,1840.23 1861.5,1855.9 1861.5,1945.9 1847.17,1960.23 1666.41,1960.23 1541.18,1960.23 1519.84,1938.89 1512.18,1931.23 1472.41,1931.23 1201.41,1931.23 1198.41,1928.23 1198.41,1845.23 1203.41,1840.23
NetC23_2 on Top Layer "gn" (solid, remove dead copper, pour order 50): 1346.41,1984.23 1418.41,1984.23 1421.41,1987.23 1421.41,2004.23 1425.41,2008.23 1495.68,2008.23 1503.68,2016.23 1503.68,2057.96 1501.41,2060.23 1430.41,2060.23 1421.41,2069.23 1354.41,2069.23 1345.41,2078.23 1345.41,2122.23 1341.41,2126.23 1274.41,2126.23 1271.41,2123.23 1271.41,2081.23 1259.41,2069.23 1202.41,2069.23 1197.41,2064.23 1197.41,1989.23 1202.41,1984.23
GND_P on Top Layer "gn" (solid, remove dead copper, pour order 48): 1348.41,2260.23 1348.41,2475.23 1342.41,2481.23 1239.41,2481.23 1231.41,2473.23 1231.41,2394.23 1208.41,2371.23 1208.41,2293.23 1200.41,2285.23 1194.99,2279.81 1134.41,2279.81 1061.81,2279.81 1054,2272 1054,2201 1062.77,2192.23 1201.41,2192.23 1235.75,2192.23 1240.75,2197.23 1240.75,2230.57 1247.41,2237.23 1333.41,2237.23 1348.41,2252.23
GND_P on Top Layer "gn" (solid, remove dead copper, pour order 46): 2591.5,3159.62 2591.5,3002.62 2596.5,2997.62 2675.5,2997.62 2677.68,2999.81 2677.68,3026.81 2685.5,3034.62 2802.24,3034.62 2802.56,3025.62 2802.56,3018.33 2802.56,2994.62 2827.56,2969.62 2858.34,2969.62 2869.5,2958.41 2869.5,2906.62 2865.5,2902.62 2773.5,2902.62 2769.5,2898.62 2769.5,2864.79 2773.5,2860.79 2891.67,2860.79 2899.5,2868.62 2913.5,2882.62 2913.5,3018.62 2906.5,3025.62 2866.5,3025.62 2852.5,3039.62 2852.5,3092.62 2846.5,3098.62 2746.5,3098.62 2739.5,3105.62 2739.5,3143.62 2735.5,3147.62 2720.5,3162.62 2668.5,3162.62 2594.5,3162.62
GND_P on Top Layer "gn" (solid, remove dead copper, pour order 44): 2551.5,2826.62 2339.5,2826.62 2334.5,2821.62 2334.5,2762.62 2342.5,2754.62 2688.5,2754.62 2692.5,2758.62 2692.5,2820.62 2676.5,2836.62 2587.5,2836.62 2577.5,2826.62
NetL3_1 on Top Layer "net" (solid, remove dead copper, pour order 38): 2461.68,3057.85 2324.68,3057.85 2316.5,3049.67 2316.5,2973.03 2322.68,2966.85 2456.68,2966.85 2466.68,2976.85 2466.68,3052.85
VOUT_DCDC_P on Top Layer "net" (solid, remove dead copper, pour order 36): 2128.46,3301.62 2724.5,3301.62 2731.5,3294.62 2731.5,3243.62 2730.5,3242.62 2687.5,3242.62 2678.5,3242.62 2674.5,3238.62 2674.5,3204.62 2654.73,3184.85 2130.68,3184.85 2116.68,3198.85 2116.68,3289.85
NetC7_1 on Top Layer "net" (solid, remove dead copper, pour order 34): 2260.3,2052.3 1955,2052.3 1946,2061.3 1946,2138.3 1952,2144.3 2042,2144.3 2053,2155.3 2053,2192.3 2055,2194.3 2266.7,2194.3 2288,2173 2288,2080
GND_P on Top Layer "net" (solid, remove dead copper, pour order 32): 1989.13,2935.88 1788.13,2935.88 1739.13,2984.88 1666,2984.88 1659,2991.88 1659,3268 1652.13,3274.88 1535.13,3274.88 1532.13,3271.88 1532.13,3192.55 1537.13,3187.55 1542,3182.68 1542,2915.75 1532.13,2905.88 1118.13,2905.88 991.53,2905.87 987,2910.4 987,2928.4 982,2933.4 961,2933.4 945,2933.4 940,2928.4 940,2900.06 940,2816.4 955.53,2800.88 1075.53,2800.88 1275.13,2800.88 2020.13,2800.88 2030.13,2810.88 2030.13,2930.88 2025.13,2935.88
VCC_P on Top Layer "net" (solid, remove dead copper, pour order 24): 1315.13,3075.88 908.53,3075.87 895,3089.4 895,3285.4 907.47,3297.87 1201.13,3297.88 1364.13,3297.88 1370,3292 1370,3195.4 1331,3156.4 1331,3118.55 1331,3085.4 1321.47,3075.87
NetC1_2 on Top Layer "net" (solid, remove dead copper, pour order 22): 1415.13,2989.88 1518.13,2989.88 1521,2987 1521,2932.75 1518.13,2929.88 1133.13,2929.88 1121.13,2941.88 1121.13,3014.88 1131.13,3024.88 1327.13,3024.88 1350.13,3001.88 1362.13,2989.88
NetC18_2 on Top Layer "g" (solid, remove dead copper, pour order 4): 474.78,2366.35 494.11,2347.02 494.11,1824.11 454,1784 77,1784 35.3,1825.7 35.3,2534.87 80.78,2580.35 291.78,2580.35 300.66,2589.23 300.66,2681.23 305.78,2686.35 348.78,2686.35 354.11,2681.02 354.11,2590.02 365.73,2578.4 402.49,2578.4 414.11,2566.78 414.11,2544.35 426.06,2532.4 595,2532.4 601.78,2525.62 601.78,2486.18 595.95,2480.35 155.11,2480.35 119.11,2444.35 119.11,1898.89 147,1871 395,1871 414.11,1890.11 414.11,2363.68 416.78,2366.35
NetC13_1 on Top Layer "net" (solid, remove dead copper, pour order 16): 677.78,2704.35 752.78,2704.35 766.78,2718.35 775.78,2727.35 775.78,2886.35 775.78,3104.62 717.78,3162.62 717.78,3233.18 729,3244.4 862,3244.4 871.78,3234.62 871.78,2663.35 828.78,2620.35 816.78,2608.35 656.78,2608.35 622.78,2608.35 580.78,2566.35 560.78,2546.35 489.78,2546.35 480.78,2546.35 476.78,2550.35 476.78,2599.35 509.78,2632.35 525.78,2648.35 525.78,2677.35 525.78,2695.35 534.78,2704.35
